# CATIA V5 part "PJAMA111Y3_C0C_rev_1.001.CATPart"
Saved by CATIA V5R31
Part number: PJAMA111Y3_C0C_rev_1.001
Source: Unknown
Bounding box of the stored display mesh (mm): x 4227.543 to 4268.943, y -491.464 to -385, z 678 to 724.353
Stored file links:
  \\solize.local\damia\dept\DDE_Design\10_order\2305701_JAMA_変換検証STEP3_お手本モデル作成\work\02_マツダ_板金\10_CATIA_V5\231211\PJAMA111Y3_C0C_rev_1.001.CATPart
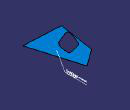
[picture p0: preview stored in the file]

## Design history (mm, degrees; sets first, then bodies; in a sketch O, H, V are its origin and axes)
TTRSSet1
f4a2d38f3ddc11d3a929006094b99c4b_11 "CATTPSSet"
Set1
  DatumSurface1 "OPEN_SHELL #622"
Body1 (main body)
